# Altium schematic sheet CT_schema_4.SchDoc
size 383 x 218 mm
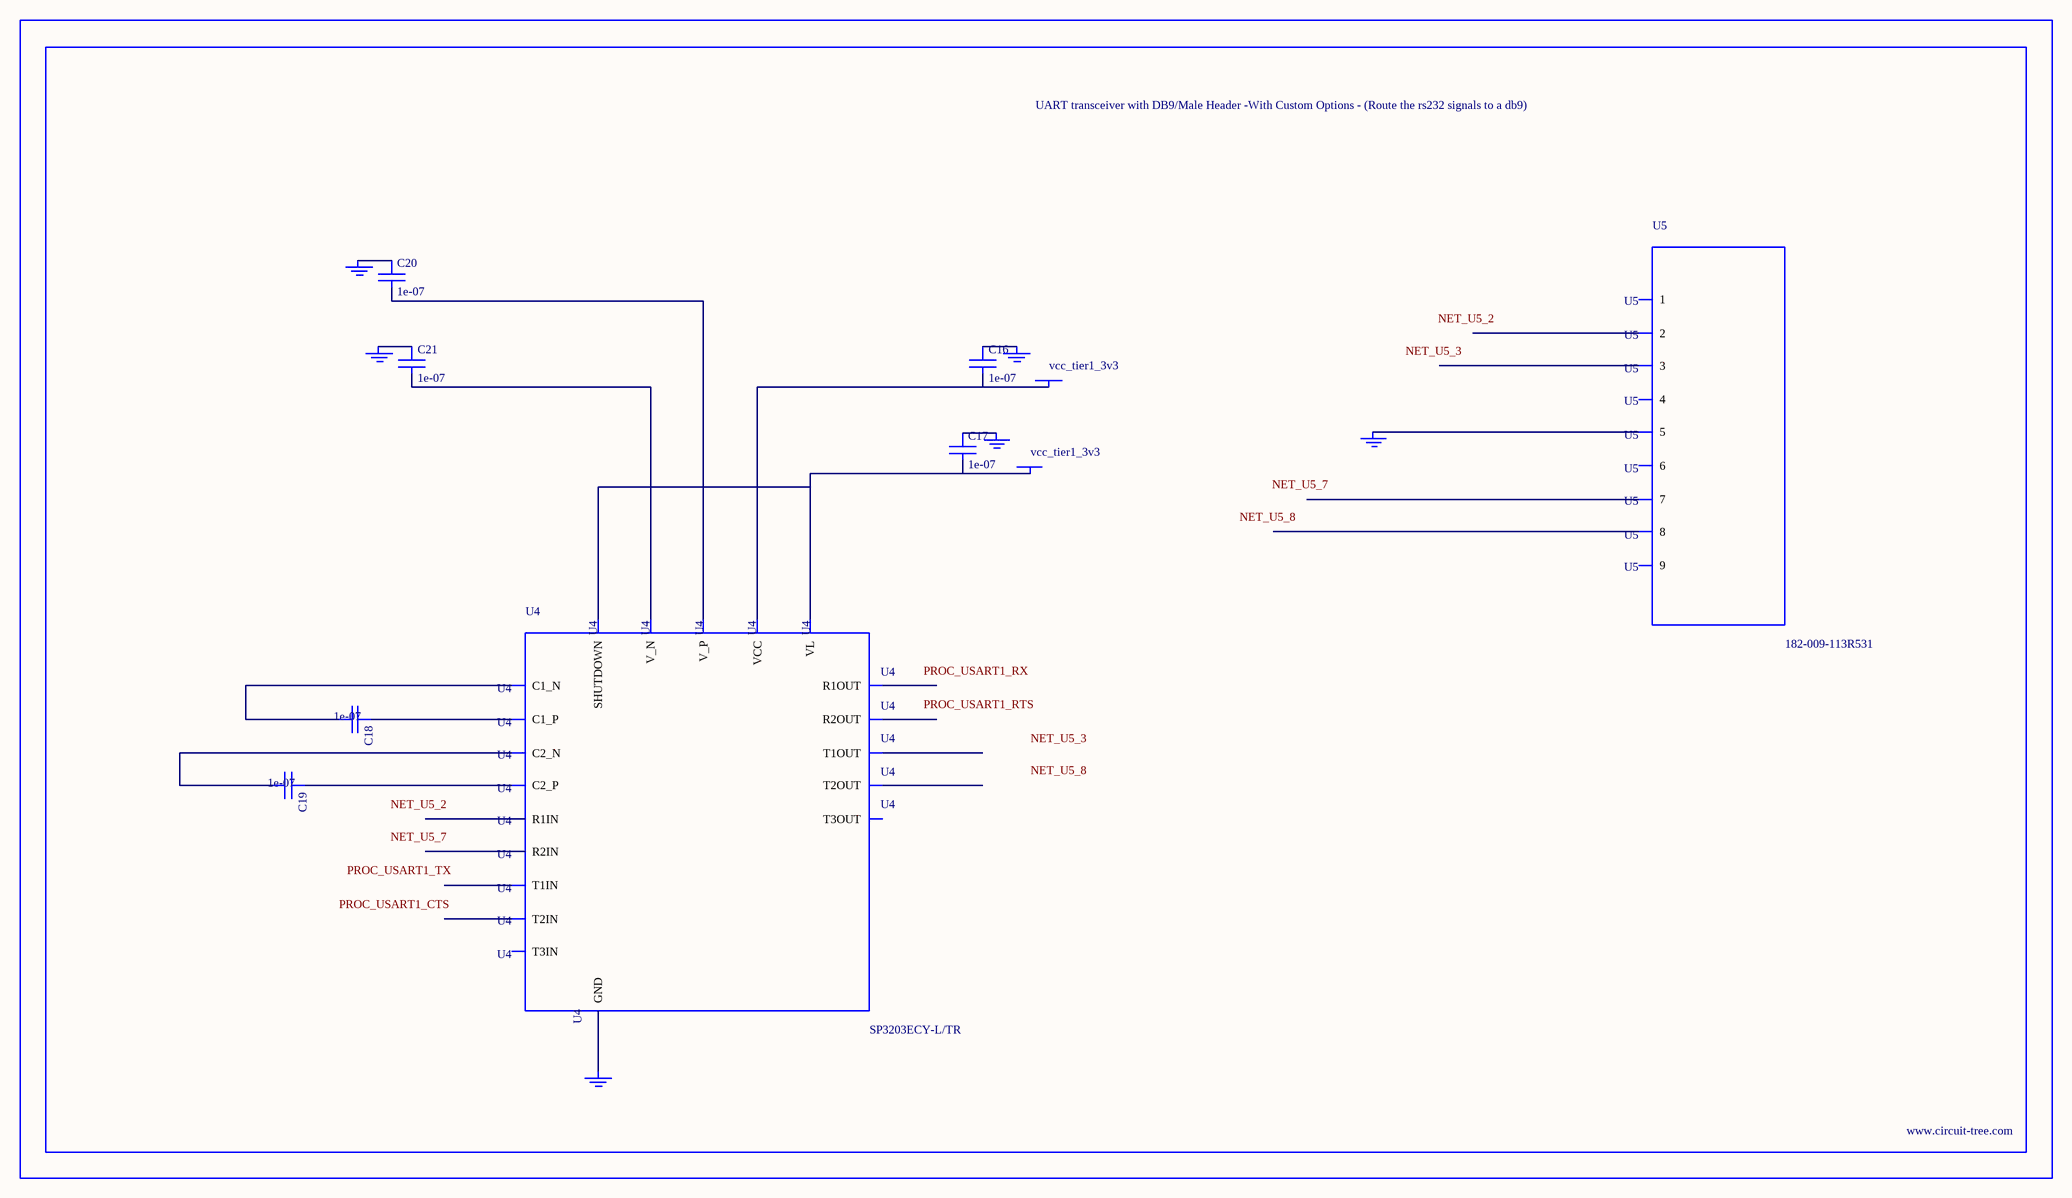
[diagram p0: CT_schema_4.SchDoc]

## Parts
BORDER3  (no value)
C16  1e-07  [C0402]
C17  1e-07  [C0402]
C18  1e-07  [C0402]
C19  1e-07  [C0402]
C20  1e-07  [C0402]
C21  1e-07  [C0402]
GND_INSTANCE_3_0  (no value)
GND_INSTANCE_3_1  (no value)
GND_INSTANCE_3_2  (no value)
GND_INSTANCE_3_3  (no value)
GND_INSTANCE_3_4  (no value)
GND_INSTANCE_3_5  (no value)
POWER_INSTANCE_3_0  vcc_tier1_3v3
POWER_INSTANCE_3_1  vcc_tier1_3v3
U4  SP3203ECY-L/TR  [TSSOP20-I]
U5  182-009-113R531  [182-009-MALE]

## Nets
NetC16_1: C16.1 GND_INSTANCE_3_3.0(GND)
NetC16_2: C16.2 POWER_INSTANCE_3_1.0(PWR) U4.19(VCC)
NetC17_1: C17.1 GND_INSTANCE_3_2.0(GND)
NetC17_2: C17.2 POWER_INSTANCE_3_0.0(PWR) U4.12(VL) U4.20(SHUTDOWN)
NetC18_1: C18.1 U4.1(C1_P)
NetC18_2: C18.2 U4.3(C1_N)
NetC19_1: C19.1 U4.4(C2_P)
NetC19_2: C19.2 U4.5(C2_N)
NetC20_1: C20.1 GND_INSTANCE_3_0.0(GND)
NetC20_2: C20.2 U4.2(V_P)
NetC21_1: C21.1 GND_INSTANCE_3_1.0(GND)
NetC21_2: C21.2 U4.6(V_N)
NetGND_INSTANCE_3_4_0: GND_INSTANCE_3_4.0(GND) U4.18(GND)
NetGND_INSTANCE_3_5_0: GND_INSTANCE_3_5.0(GND) U5.5

Not connected (* = marked no-connect by the designer): U4 7(T1IN) 8(T2IN) 9(T3IN) 10(R2OUT) 11(R1OUT) 13(R2IN) 14(R1IN) 15(T3OUT) 16(T2OUT) 17(T1OUT); U5 1 2 3 4 6 7 8 9

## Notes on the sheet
- Labels drawn without touching a wire or pin: NET_U5_2, NET_U5_3, NET_U5_7, NET_U5_8, PROC_USART1_CTS, PROC_USART1_RTS, PROC_USART1_RX, PROC_USART1_TX

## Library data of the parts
BORDER3 = BORDER_PAGE3
C16-C21 = C0402C104K3RACTU
GND_INSTANCE_3_0-GND_INSTANCE_3_5 = GND
POWER_INSTANCE_3_0 POWER_INSTANCE_3_1 = PWR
